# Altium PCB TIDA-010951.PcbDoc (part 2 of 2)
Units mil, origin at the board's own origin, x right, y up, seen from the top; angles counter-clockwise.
Board outline 3346.46 x 3346.46 mil, 2 copper layers (Top Layer, Bottom Layer), stack 62 mil thick; 118 components, 74 nets, 305 pads, 166 vias.
Unrouted connection lines stored in the file: 4.
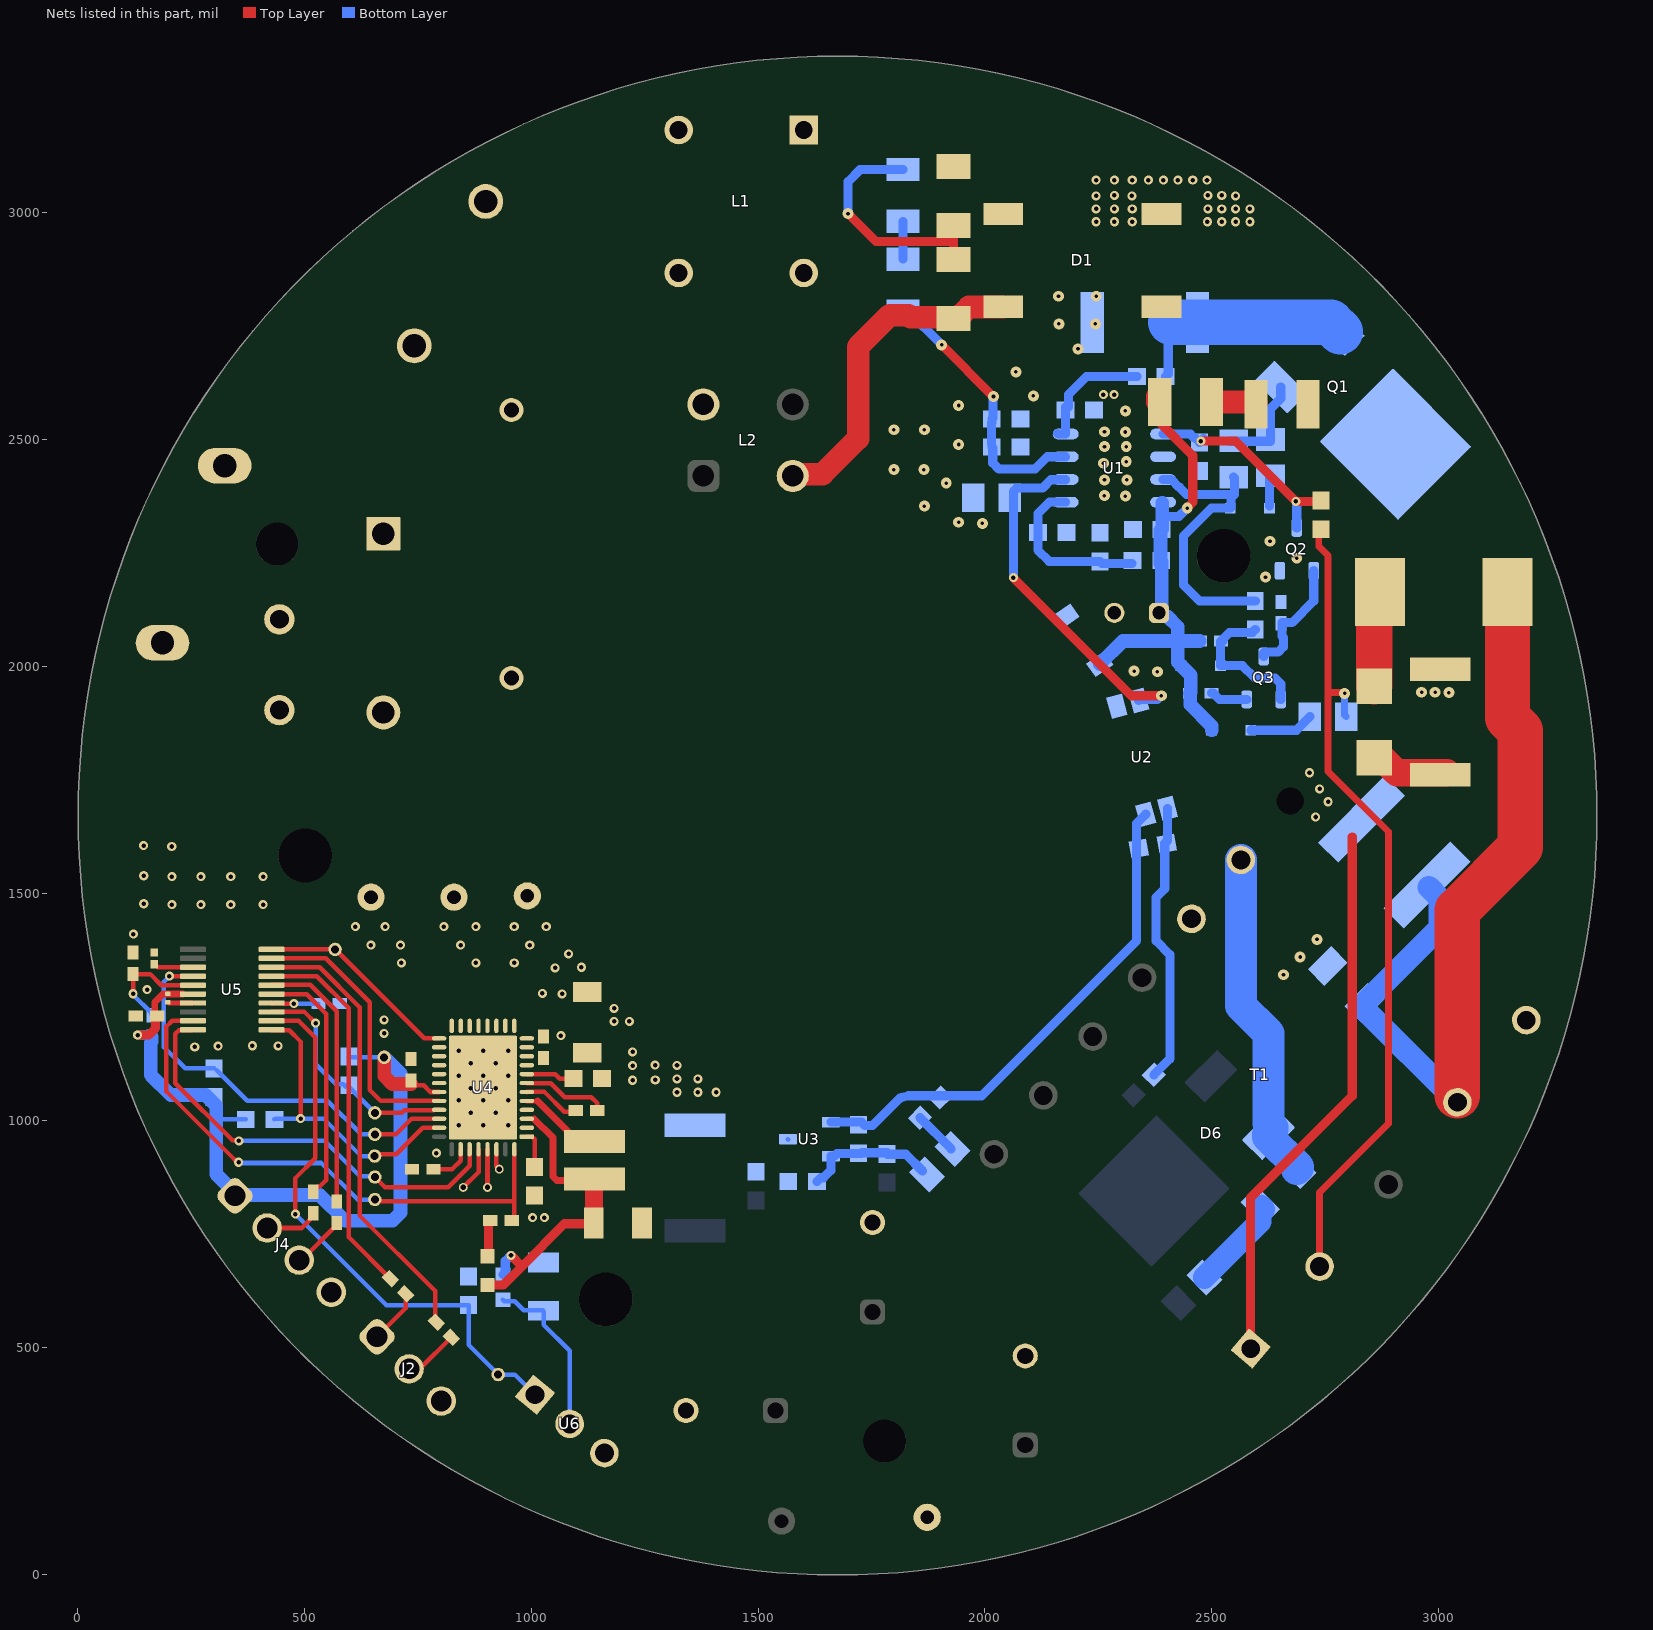
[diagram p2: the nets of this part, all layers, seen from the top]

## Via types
v1: diameter 20, hole 10, Top Layer to Bottom Layer, tented both sides, 70 vias
v2: diameter 20, hole 10, Top Layer to Bottom Layer, 51 vias
v3: diameter 24, hole 8, Top Layer to Bottom Layer, tented both sides, 45 vias

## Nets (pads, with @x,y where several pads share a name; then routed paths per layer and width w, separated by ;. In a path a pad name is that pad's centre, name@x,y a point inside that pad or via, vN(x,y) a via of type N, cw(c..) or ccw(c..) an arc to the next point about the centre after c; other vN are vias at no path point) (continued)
AVDD: C23.1 C24.2 C27.1 J4.1 R24.2 R26.2 R27.2 R34.2 TP7.1 U4.27 U5.6 | length 1746.8
  Top Layer w10: C27.1@735.64,1080.4 738.54,1077.5 763.49,1077.5 778.06,1062.92 U4.27@797.48,1062.92
  Top Layer w15: C23.1@170.7,1240.78 170.7,1260.47 188.78,1278.55 U5.6@232.4,1278.55
  Top Layer w20: v1(133.23,1188.16) 157.02,1188.16 172.69,1203.83 172.69,1228.5 174.5,1230.31 C23.1@176.18,1230.31
  Top Layer w30: TP7.1@676.21,1139.19 676.21,1098.14 693.79,1080.57 735.47,1080.57 C27.1@735.64,1080.4
  Bottom Layer w10: R24.2@158.17,1191.24 R24.2@164.37,1185.04 ; 305.94,1002.77 R26.2@371.26,1002.77 ; 404.97,836.08 407.52,838.63 ; R34.2@598.74,1140.79 600.34,1139.19 TP7.1@676.21,1139.19
  Bottom Layer w20: v1(133.23,1188.16) 155.09,1188.16 R24.2@158.17,1191.24
  Bottom Layer w30: R24.2@164.37,1185.04 163.62,1184.29 163.62,1173.44 161.65,1171.47 161.65,1100.57 206,1056.23 282.67,1056.23 305.94,1032.96 305.94,1002.77 305.94,882.34 347.67,840.6 347.67,836.08 404.97,836.08 533.97,836.08 590.66,779.38 694.66,779.38 712.23,796.96 712.23,1104.24 TP7.1@677.29,1139.19
BRAKE: TP10.1 U4.35 U5.10 | length 950.6
  Top Layer w10: U5.10@255.03,1199.95 254.13,1199.05 224.11,1199.05 216.11,1191.05 216.11,1082.35 342.02,956.44 355.22,956.44 v1(356.3,955.36) ; TP10.1@655.8,875.67 678.12,853.35 817.59,853.35 864.53,900.28 U4.35@864.53,936.82
  Bottom Layer w10: v1(356.3,955.36) 544.89,955.36 622.93,877.32 654.15,877.32 TP10.1@655.8,875.67
DRVOFF: TP6.1 U4.21 U5.20 | length 450.4
  Top Layer w10: U5.20@428.26,1377.12 TP6.1@568.19,1377.12 764.28,1181.03 U4.21@797.48,1181.03
FG: R34.1 TP11.1 U4.29 U5.13 | length 520
  Top Layer w10: U5.13@428.26,1239.32 500.61,1239.32 v1(525.41,1214.52) ; TP11.1@655.8,1017.06 714.95,1017.06 721.04,1023.15 785.98,1023.15 786.16,1023.33 786.61,1023.33 786.84,1023.55 U4.29@797.48,1023.55
  Bottom Layer w10: v1(525.41,1214.52) 525.41,1124.4 570.02,1079.79 586.56,1079.79 591.66,1074.69 596.75,1079.79 R34.1@598.74,1077.79 ; R34.1@598.38,1074.48 TP11.1@655.8,1017.06
GND: C2.1 C5.2 C6.2 C7.2 C8.2 C20.2 C21.2 C22.2 C23.2 C24.1 C25.1 C27.2 C28.2 C30.2 C31.2 C32.2 GND.1 J2.3 J4.4 R23.1 R25.2 R35.2 T1.8 U3.3 U4.2 U4.4 U4.12 U4.15 U4.18 U4.22 U4.23 U4.24 U4.25 U4.26 U4.41 U5.7 U6.3 | length 57
  Top Layer w10: C24.1@199.62,1260.5 200.44,1260.5 201.94,1259.01 U5.7@255.04,1259.01
  Bottom Layer w10: U3.3@1565.92,958.99 U3.3@1566.6,958.31
  other v1: 1003.56,786.33 1029.47,786.2 791.13,928.21 258.98,1162.35 310.35,1164.06 385.99,1164.83 442.79,1164.74 153.8,1288.53 1110.74,1337.75 123.65,1410.79 208.5,1475.89 272.28,1475.89 338.22,1475.89 409.45,1475.89 146.56,1477.77 208.5,1537.52 272.28,1537.52 338.22,1537.52 409.45,1537.52 146.56,1539.41 208.31,1603.87 146.37,1605.76
  other v2: 840.27,989.63 894.75,989.63 949.24,989.63 867.51,1016.98 921.99,1016.98 840.27,1044.32 894.75,1044.32 949.24,1044.32 867.51,1071.66 921.99,1071.66 840.27,1099 894.75,1099 949.24,1099 867.51,1126.35 921.99,1126.35 840.27,1153.69 894.75,1153.69 949.24,1153.69 1065.66,1187.01 676.21,1191.99 1182.9,1218.73 1216.47,1218.73 676.21,1221.68 1182.9,1247.16 1068.17,1279.2 1025.02,1280.01 1052.81,1336.28 1082.54,1367.27
  other v3: 2657.64,1321.25 2694.49,1360.36 2731.54,1399.13
IR: C32.1 TP15.1 U5.12 U6.1 | length 1262.2
  Top Layer w10: U5.12@428.26,1219.64 487.68,1219.64 524.26,1183.06 524.26,916.8 480.81,873.35 v1(480.81,793.8)
  Bottom Layer w10: v1(480.81,793.8) 681.1,593.5 C32.1@862.2,593.5 862.2,505.73 TP15.1@927.54,440.4 963.78,440.4 1008.26,395.92 U6.1@1008.39,395.92
LINE: pad.2 RT1.1
NetC1_1: C1.1 F1.1 L1.3 MOV1.2
NetC1_2: C1.2 L1.2 MOV1.1 RT1.2
NetC2_2: C2.2 C3.1 D1.1 D2.2 R1.2 T1.4 | length 1842.9
  Top Layer w100: T1.4@3040.9,1054.39 3040.9,1463.56 3179.6,1602.26 3179.6,1859.17 3151.32,1887.46 D2.2@3151.32,2164.37 D2.2@3151.32,2184.37
  Bottom Layer w50: C3.1@2977.56,1514.28 3002.46,1489.38 3002.46,1425.26 2829.79,1252.59 2829.19,1252 T1.4@3040.9,1040.29
NetC4_1: C4.1 R3.2 | length 215.2
  Bottom Layer w50: C4.1@2483.3,654.41 2606.41,777.52 2606.41,796.08 2614.07,803.74 2614.07,804.57 R3.2@2606.41,812.23
NetC11_1: C11.1 R7.1 R8.2 U1.1 | length 371.5
  Bottom Layer w20: U1.1@2177.86,2362.57 2177.78,2362.49 2142.08,2362.49 2116.7,2337.12 C11.1@2116.7,2295.14 2116.7,2256.68 2141.23,2232.15 R8.2@2253.26,2232.15 2258.24,2227.17 R7.1@2323.82,2227.17
NetC12_2: C12.2 Q2.3 R9.1 U1.5 | length 475.3
  Top Layer w20: v1(2475.8,2497.02) 2552.18,2497.02 v1(2685.02,2364.19) 2733.54,2364.19 R9.1@2735.19,2365.84
  Bottom Layer w20: U1.5@2392.43,2512.57 2452.43,2512.57 2461.25,2503.75 2464.15,2503.75 2472.85,2495.05 C12.2@2472.85,2494.07 v1(2475.8,2497.02) C12.2@2481.55,2502.77 ; v1(2685.02,2364.19) 2686.96,2362.24 Q2.3@2686.96,2305.8
NetC13_1: C13.1 R10.1 R13.2 U1.3 | length 596.9
  Top Layer w20: v3(1904.45,2709.03) 1904.77,2709.03 2018.59,2595.2 v3(2018.91,2595.2)
  Bottom Layer w20: R10.1@1818.98,2783.67 1829.81,2783.67 v3(1904.45,2709.03) ; C13.1@2014.31,2491.8 2014.31,2503.72 2014.75,2537.24 2015.03,2537.52 R13.2@2015.03,2545.66 2016.01,2545.66 2018.14,2547.79 2018.14,2594.43 v3(2018.91,2595.2) ; C13.1@2015.03,2483.65 2017.1,2481.58 2017.1,2449.05 2030.89,2435.26 2110,2435.26 2137.31,2462.57 U1.3@2177.86,2462.57
NetC15_1: C15.1 R15.2 U1.4 | length 282.3
  Bottom Layer w20: U1.4@2160.43,2514.24 2162.11,2512.57 U1.4@2177.86,2512.57 2177.12,2513.31 C15.1@2177.12,2571.91 ; C15.1@2177.38,2565.24 2183.91,2571.78 2183.91,2599.52 2223.51,2639.12 R15.2@2335.09,2639.12
NetC16_1: C16.1 D11.2 Q3.1 R18.2 | length 322.9
  Bottom Layer w20: R18.2@2520.14,2056.7 2518.75,2055.3 D11.2@2518.75,2002.38 2567.31,2002.38 2594.51,1975.18 2638.62,1975.18 2651.59,1962.2 Q3.1@2651.59,1927.93 ; R18.2@2524.08,2056.7 2525.89,2058.51 2525.89,2062.44 2539.07,2075.62 2589.02,2075.62 C16.1@2595.49,2082.1
NetC16_2: C16.2 D9.1 R12.1 U1.7 | length 653.7
  Bottom Layer w20: U1.7@2392.43,2412.57 2410.14,2412.57 2427.19,2395.52 2428.04,2395.52 2443.77,2379.79 2550.13,2379.79 ; R12.1@2548.03,2417.57 2550.13,2415.48 2550.13,2379.79 ; C16.2@2595.49,2145.09 2472.23,2145.09 2436.98,2180.34 2436.98,2287.39 2498.88,2349.29 D9.1@2540.35,2349.29 2542.17,2351.1 2542.17,2371.82 2550.13,2379.79
NetC17_1: C17.1 R19.1 R21.1 U2.2 U3.1 | length 1131
  Bottom Layer w20: U3.1@1660.41,996.39 1728.07,996.39 1735.55,988.91 1752.12,988.91 1812.23,1049.02 ccw(c1804.43,1067.43) 1815.56,1050.82 1831.71,1054.7 1859.31,1054.7 1883.06,1054.7 1912.49,1054.7 1992.56,1054.7 2334.01,1396.15 2334.01,1599.47 2334.01,1654.71 U2.2@2354.18,1674.88
NetC17_2: C17.2 C18.1 R16.1 R23.2 U3.2 | length 294.2
  Bottom Layer w20: R23.2@1629.59,865.38 1638.29,874.08 1644.12,874.08 1660.41,890.36 U3.2@1660.41,921.59 1668.28,921.59 1674.19,927.49 C17.2@1728.07,927.49 ; C17.2@1728.74,929.15 1784.34,929.15 R16.1@1784.34,926.67 1785.21,925.8 1825.43,925.8 C18.1@1862.34,888.89
NetC18_2: C18.2 R21.2 | length 100.3
  Bottom Layer w10: C18.2@1925.52,937.7 C18.2@1928.86,937.7
  Bottom Layer w20: R21.2@1856.92,1006.3 C18.2@1925.52,937.7
NetC19_1: C19.1 U1.2 U2.4 | length 804.2
  Top Layer w20: v1(2062.46,2196.06) 2322.62,1935.9 v3(2388.52,1935.9)
  Bottom Layer w20: v1(2062.46,2196.06) 2062.46,2386.04 2069.74,2393.32 2126.81,2393.32 2145.38,2411.88 2177.17,2411.88 U1.2@2177.86,2412.57 ; U2.4@2338.79,1925.5 2341.3,1928.01 2379.55,1928.01 2387.44,1935.9 v3(2388.52,1935.9)
NetC20_1: C20.1 C21.1 C26.1 R33.2 U4.9 U4.10 U4.11
  other v1: 1321.49,1062.42 1367.47,1062.42 1407.83,1062.42 1321.49,1092.04 1367.47,1092.04 1321.49,1121.66
  other v2: 1223.81,1088.91 1273.57,1089.82 1223.81,1121.06 1273.27,1121.98 1223.81,1151.28
NetC25_2: C25.2 U5.3 | length 88
  Top Layer w10: C25.2@170.06,1345.03 177.35,1337.75 U5.3@255.03,1337.75
NetC26_2: C26.2 U4.8 | length 106.5
  Top Layer w10: U4.8@990.63,1102.29 1053.36,1102.29 1063.46,1092.2 C26.2@1092.98,1092.2
NetC28_1: C28.1 U4.1 | length 88.4
  Top Layer w10: U4.1@990.63,964.5 1002.11,964.5 1007.97,958.64 C28.1@1007.97,890
NetC29_1: C29.1 U4.6 | length 127.1
  Top Layer w10: U4.6@990.63,1062.92 990.7,1062.99 1029.47,1062.99 1072.96,1019.5 1095.95,1019.5 C29.1@1098.61,1022.16
NetC29_2: C29.2 U4.7 | length 189.9
  Top Layer w10: U4.7@990.63,1082.61 1043.52,1082.61 1074.46,1051.67 1132.76,1051.67 1145.86,1038.57 C29.2@1145.86,1022.16
NetC30_1: C30.1 R24.1 U5.5 | length 254.2
  Top Layer w10: v1(123.03,1279.37) C30.1@123.03,1322.83 160.95,1322.83 185.41,1298.38 U5.5@255.03,1298.38 ; C30.1@128.66,1313.27 C30.1@128.66,1317.67
  Bottom Layer w10: v1(123.03,1279.37) 123.03,1277.56 164.37,1236.22 R24.1@164.37,1232.28
NetC31_1: C31.1 R29.1 U6.2 | length 374.2
  Bottom Layer w10: R29.1@937.99,605.31 941.18,602.13 963.87,602.13 983.69,582.31 1025.85,582.31 C31.1@1027.28,580.89 ; C31.1@1025.59,580.89 1027.37,579.11 1027.37,550.09 1084.99,492.48 U6.2@1084.99,330.74
NetD1_3: D1.3 D3.2 L1.1
NetD1_4: D1.4 D4.2 L2.2 | length 742.6
  Top Layer w50: L2.2@1576.4,2420.3 1580.39,2424.29 1642.24,2424.29 1720.49,2502.55 1720.49,2704.92 1790.18,2774.61 1831.6,2774.61 1836.11,2770.1 1927.81,2770.1 D4.2@1930.37,2767.54 1940.21,2767.54 1964.95,2792.28 2039.79,2792.28 D1.4@2040.29,2792.78
NetD2_1: D2.1 D5.1 | length 203.1
  Top Layer w80: D5.1@2857.95,1956.95 D2.1@2857.95,2160.09
NetD3_1: D3.1 D4.1 R5.2 | length 564.2
  Top Layer w20: v3(1698.34,2998.11) 1760.06,2936.38 1918.66,2936.38 1918.66,2960.73 D3.1@1930.37,2972.44 D4.1@1930.37,2897.46
  Bottom Layer w20: v3(1698.34,2998.11) 1698.34,3068.81 1725,3095.47 R5.2@1818.98,3095.47
NetD5_2: D5.2 R2.2 | length 156.8
  Top Layer w60: D5.2@2874.61,1799.47 2907.61,1766.48 R2.2@3017.74,1766.48
NetD6_3: D6.3 R3.1 T1.7 | length 743.4
  Bottom Layer w70: T1.7@2563.83,1574.22 2563.83,1252.9 2624.82,1191.92 2624.82,993.87 2633.78,984.91 2633.78,979.95 D6.3@2624.82,970.99 2623.37,969.54 2623.37,964.59 2690.07,897.89 2690.07,895.88 R3.1@2687.15,892.96
NetD7_2: D7.2 R6.1 | length 144.9
  Bottom Layer w20: D7.2@2587.68,1861.85 D7.2@2585.87,1860.04 2685.93,1860.04 R6.1@2715.86,1889.97
NetD9_2: D9.2 R11.1 | length 63.7
  Bottom Layer w20: D9.2@2626.89,2353.68 D9.2@2626.93,2353.73 ; R11.1@2626.93,2417.21 D9.2@2626.93,2353.73 ; D9.2@2627.04,2353.84 D9.2@2626.93,2353.73
NetD14_1: D14.1 R36.2 | length 81.8
  Top Layer w20: D14.1@903.9,700.76 906.18,703.04 R36.2@906.18,781.65
NetJ2_1: J2.1 R28.2 | length 123
  Top Layer w10: J2.1@660.51,523.54 723.4,586.42 723.4,602.94 726.18,605.72 726.18,615.36 R28.2@723.4,618.14
NetJ2_2: J2.2 R31.2 | length 122.1
  Top Layer w10: J2.2@731.22,452.83 755.03,452.83 R31.2@824.54,522.33
NetJ4_2: J4.2 R30.2 | length 112.4
  Top Layer w10: J4.2@418.38,763.3 494.64,763.3 R30.2@520.16,788.83
NetJ4_3: J4.3 R32.2 | length 114
  Top Layer w10: J4.3@494.18,692.59 572.04,770.45 R32.2@572.04,774.39
NetL1_4: L1.4 L2.3
NetL3_1: L3.1 U4.5 | length 134.9
  Top Layer w10: U4.5@990.63,1042.98 1014.35,1042.98
  Top Layer w15: 1014.35,1042.98 1080.52,976.81 1080.52,969.86 L3.1@1088.08,962.3
NetQ1_1: Q1.1 R11.2 R12.2 | length 213.7
  Bottom Layer w20: R12.2@2540.28,2496.77 R11.2@2629.09,2496.77 ; R11.2@2629.09,2500.52 2629.09,2568.25 2651.75,2590.91 Q1.1@2651.75,2615.99
NetQ1_2: Q1.2 R2.1 T1.5
  other v3: 2962.17,1943.69 2991.85,1943.69 3022.15,1942.91
NetQ1_3: Q1.3 R15.1 R17.2 | length 506
  Bottom Layer w20: R15.1@2398.08,2639.12 2403.76,2644.8 2403.76,2752.86 2409.45,2758.54
  Bottom Layer w100: 2409.45,2758.54 2762.11,2758.54 Q1.3@2782.79,2737.86
NetQ2_1: Q2.1 Q3.3 R22.2 | length 267.9
  Bottom Layer w20: Q3.3@2614.19,2022.42 2614.19,2030.3 2616,2032.11 2645.92,2032.11 2657.63,2043.82 2657.63,2063.82 2654.26,2067.19 2654.26,2097.28 2676.56,2097.28 2724.36,2145.08 Q2.1@2724.36,2211.32
NetQ3_2: Q3.2 R20.2 | length 83.4
  Bottom Layer w20: R20.2@2499.06,1941.58 2503,1941.58 2516.65,1927.93 Q3.2@2576.79,1927.93
NetR1_1: R1.1 R4.2 | length 107.6
  Top Layer w50: R4.2@2499.22,2588.32 2499.22,2583.88 2499.81,2583.29 2596.81,2583.29 2597.4,2582.7 R1.1@2597.4,2578.25
NetR5_1: R5.1 R10.2 | length 83.5
  Bottom Layer w20: R10.2@1818.98,2897.84 R5.1@1818.98,2981.3
NetR6_2: R6.2 R9.2 T1.2 | length 1838.7
  Top Layer w15: R9.2@2735.19,2302.85 2735.19,2265.61 2755.86,2244.94 2755.86,1942.91 ; T1.2@2737.22,678.38 2737.22,841.24 2889.06,993.08 2889.06,1636.32 2755.86,1769.52 2755.86,1942.91 ; v3@2790.68,1942.91 2755.86,1942.91
  Bottom Layer w15: v3(2792.32,1941.27) 2792.32,1893.52 R6.2@2795.86,1889.97
NetR14_1: R14.1 R19.2 U2.1 | length 625.1
  Bottom Layer w20: R14.1@2372.04,1100.59 2407.58,1136.13 2407.58,1365.45 2377.05,1395.99 2377.05,1491.81 2396.04,1510.81 2396.04,1610.41 2402.48,1616.84 U2.1@2402.48,1687.82
NetR25_1: R25.1 U4.34 | length 93
  Top Layer w10: R25.1@785.04,892.48 825.86,892.48 844.84,911.47 U4.34@844.84,936.82
NetR35_1: R35.1 U5.14 | length 103.6
  Top Layer w10: U5.14@428.26,1259.01 429.17,1258.1 453.62,1258.1 453.95,1257.77 v2(477.23,1257.77)
  Bottom Layer w10: v2(477.23,1257.77) R35.1@531.38,1257.77
NetTP9_1: TP9.1 U4.38 | length 46.4
  Top Layer w10: U4.38@923.58,936.82 923.58,899.2 TP9.1@929.82,892.96
NetTP16_1: TP16.1 U4.37 | length 84.1
  Top Layer w10: U4.37@903.9,936.82 U4.37@903.9,936.82 TP16.1@903.94,852.73
NetTP17_1: TP17.1 U4.36 | length 98
  Top Layer w10: TP17.1@850.61,852.73 884.21,886.34 U4.36@884.21,936.82
NetTPA_1: TPA.1 U4.13 U4.14
  other v2: 962.95,1347.59 997.01,1386.48 962.95,1427.46 1033.34,1427.46
NetTPB_1: TPB.1 U4.16 U4.17
  other v2: 878.52,1347.59 844.84,1386.48 807.75,1427.46 878.52,1427.46
NetTPC_1: TPC.1 U4.19 U4.20
  other v2: 714.42,1347.59 647.19,1386.48 712.25,1386.48 612.83,1427.46 678.56,1427.46
nFAULT: R36.1 TP12.1 U4.40 U5.9 | length 1232.6
  Top Layer w10: U5.9@261.39,1220.14 209.47,1220.14 196.65,1207.32 196.65,1064.06 347.62,913.09 348.05,913.09 353.05,908.09 v1@355.35,908.09 ; TP12.1@655.8,826.04 659.27,822.57 962.95,822.57 ; R36.1@962.95,783.46 962.95,822.57 ; U4.40@962.95,936.82 962.95,822.57
  Bottom Layer w10: v1(355.76,908.09) 357.35,906.5 537.26,906.5 617.72,826.04 TP12.1@655.8,826.04
NTRL: F1.2 pad.3
PGND: C3.2 C9.2 C11.2 C12.1 C13.2 C14.2 C15.2 C19.2 D1.2 D8.2 Q2.2 R8.1 R13.1 R17.1 R22.1 T1.1 U1.6 U2.3 | length 1220.2
  Top Layer w20: T1.1@2585.38,497.42 2585.38,830.49 2809.18,1054.29 2809.18,1624.9
  other v1: 2260.74,2599.43 2284.58,2599.43 2245.06,2980.31 2285.2,2980.31 2324.42,2980.31 2489.84,2980.31 2521.65,2980.31 2552.17,2980.31 2583.66,2980.31 2245.06,3008.86 2285.2,3008.86 2324.42,3008.86 2491.14,3008.86 2521.65,3008.86 2552.17,3008.86 2583.66,3008.86 2245.06,3037.4 2323.82,3037.4 2552.17,3037.4 2285.2,3038.39 2491.14,3038.39 2521.65,3038.39 2245.06,3071.85 2285.2,3071.85 2324.42,3071.85 2359.97,3071.85 2393.12,3071.85 2425.13,3071.85 2457.71,3071.85 2489.17,3071.85
  other v2: 2728.44,1668.86 2755.86,1702.5 2737.22,1730.71 2714.99,1766.34
  other v3: 2379.75,1988.75 2328.78,1990.24 2618.06,2197.23 2686.96,2238.88 2627.91,2276.28 1994.35,2315.84 1942.02,2318.2 1866.62,2353.84 2309.4,2375.65 2262.97,2376.85 1914.62,2404.49 2263.29,2411.61 2312.52,2411.61 1799.3,2434.08 1865.24,2434.08 2261.03,2448.29 2311.26,2451.88 2263.29,2484.99 2311.26,2484.99 1942.02,2489.68 2263.29,2517.72 2309.4,2517.12 1799.3,2522.14 1866.62,2522.14 2309.4,2563.58 1942.02,2575.42 2106.58,2596.56 2068.18,2649.44 2204.83,2700.23 2162.74,2755.42 2243.32,2755.2 2162.11,2816.28 2245.06,2816.28
RX: R28.1 U5.17 | length 833.4
  Top Layer w10: U5.17@428.26,1318.06 528.11,1318.06 598.74,1247.43 598.74,742.8 R28.1@689.99,651.55
SCL: R26.1 TP13.1 U4.31 U5.11 | length 666.1
  Top Layer w10: U5.11@428.26,1199.95 429.17,1199.05 467.12,1199.05 492.08,1174.09 v1(492.08,1004.49) ; TP13.1@655.8,925.64 702.88,925.64 761.42,984.18 U4.31@797.48,984.18
  Bottom Layer w10: R26.1@434.26,1002.77 435.97,1004.49 v1(492.08,1004.49) 542.66,1004.49 625.34,921.81 TP13.1@655.32,921.81
SDA: R27.1 TP14.1 U4.30 U5.4 | length 906
  Top Layer w10: v1(203.18,1318.06) U5.4@255.03,1318.06 ; TP14.1@655.8,969.55 702.34,969.55 736.65,1003.87 U4.30@797.48,1003.87
  Bottom Layer w10: v1(203.18,1318.06) 191.08,1305.96 191.08,1161.73 237.78,1115.02 R27.1@301.42,1115.02 ; R27.1@307.21,1110.97 374.3,1043.87 551.09,1043.87 625.4,969.55 TP14.1@655.8,969.55
SPEED: U4.28 U5.19 | length 612.5
  Top Layer w10: U5.19@428.26,1357.43 547.84,1357.43 644.77,1260.5 644.77,1067.41 668.94,1043.24 U4.28@797.48,1043.24
SWCLK: R32.1 U5.16 | length 587.1
  Top Layer w10: U5.16@428.26,1299.22 513.56,1299.22 572.04,1240.74 R32.1@572.04,821.64
SWDIO: R30.1 U5.15 | length 545.9
  Top Layer w10: U5.15@428.26,1278.55 505.43,1278.55 548.26,1235.71 548.26,868.55 533.41,853.69 526.98,853.69 520.16,846.88 R30.1@520.16,842.94
TX: R31.1 U5.18 | length 994.3
  Top Layer w10: U5.18@428.26,1337.75 534.15,1337.75 622.05,1249.85 622.05,790.97 788.34,624.67 788.34,558.52 R31.1@791.13,555.74
VBK: C22.1 D14.2 L3.2 R29.2 U4.3 | length 713.6
  Top Layer w10: U4.3@990.63,1003.87 1006.89,1003.87 ; L3.2@1136.92,868.33 L3.2@1139.95,871.36
  Top Layer w15: 1006.89,1003.87 1047.94,962.81 1047.94,877.06 1056.73,868.28 L3.2@1120.99,868.28
  Top Layer w20: D14.2@903.9,637.77 938.65,637.77 981.15,680.26 ; v1(955.71,703.04) 978.49,680.26 981.15,680.26 ; C22.1@1138.51,772.64 1073.53,772.64 981.15,680.26
  Top Layer w40: C22.1@1138.51,772.64 L3.2@1138.51,869.92
  Bottom Layer w20: R29.2@937.99,660.43 943,665.44 943,690.33 v1(955.71,703.04)
VDD: C9.1 C14.1 D7.1 D8.1 D11.1 R4.1 R7.2 R18.1 R20.1 U1.8 | length 1141.3
  Top Layer w20: R4.1@2379.48,2561.3 R4.1@2388.89,2551.89 ; R4.1@2388.89,2568.31 R4.1@2388.89,2551.89 ; R4.1@2389.35,2551.43 R4.1@2388.89,2551.89 ; v3(2445.56,2349.29) 2445.56,2350.37 2457.79,2362.6 2457.79,2464.87 2388.89,2533.77 R4.1@2388.89,2551.89
  Top Layer w50: R4.1@2380.07,2583.29 R4.1@2380.07,2595.2
  Bottom Layer w20: 2390.82,2330.93 2427.2,2330.93 v3(2445.56,2349.29)
  Bottom Layer w30: D8.1@2252.88,2005.64 2303.94,2056.7 2424.71,2056.7 ; R7.2@2386.81,2227.17 2386.81,2299.99 C14.1@2389.21,2302.39 2390.82,2303.99 2390.82,2330.93 U1.8@2390.82,2360.96 ; R7.2@2389.76,2230.62 2389.76,2112.2 2390.58,2111.39 2401.3,2111.39 2424.71,2087.97 2424.71,2056.7 ; R18.1@2472.9,2056.7 2424.71,2056.7 ; D7.1@2499.26,1860.04 2499.26,1869.41 2452.57,1916.1 2452.57,1940.84 R20.1@2451.82,1941.58 2453.79,1943.55 2453.79,1980.73 D11.1@2432.14,2002.38 2424.71,2009.8 2424.71,2056.7
pads on no net: D6.1 L2.1 L2.4 T1.3 T1.6 T1.9 T1.10 T1.11 T1.12 U4.32 U4.33 U4.39 U5.1 U5.2 U5.8

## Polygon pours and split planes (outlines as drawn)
PGND on Bottom Layer "BOTTOM_LAYER_PGND_P146" (solid, pour order 146): 2690.07,1672.03 2690.07,1800 2883.93,1800 2925,1758.93 2925,1702.5 2786.83,1564.33 2738.21,1564.33 2738.21,1567.51 2690.07,1615.64
PGND on Bottom Layer "BOTTOM_LAYER_PGND_P128" (solid, remove dead copper, pour order 128): 2192.75,1961.29 2168,1996.18 2121.19,2062.15 2051.9,2127.03 1994.4,2169.78 1874.24,2231.7 1768.09,2253.82 1767.33,2663 2195.87,3091.54 2746.02,3091.54 2746.02,1893.52 2219.97,1893.52
+24V on Bottom Layer "Bottom Layer-+24V" (solid, pour order 147): 1449.82,151.65 1548.16,53.31 1601.03,0.45 1750.3,0.49 1907.91,15.06 2083.39,53.31 2137.49,65.1 2228.43,92.91 2334.78,134.29 2435.79,181.66 2468.49,591.68 2420.18,643.84 2409.72,719.61 2539.15,852.82 2493,898.98 2379.55,1012.42 2379.55,1034.51 2328.78,1085.28 2058.57,1085.28 1838.01,886.06 1707.35,886.06 1659.63,847.37 1470.03,845.16 1470.03,777.49 1295.21,777.49 1296.26,776.43 1296.26,643.84 1449.82,490.28
NetQ1_2 on Bottom Layer "BOTTOM_LAYER_NETQ1_2_P111" (solid, pour order 111): 2909.43,1863.96 3095.49,1677.9 3095.49,1241.01 3146.76,1189.74 3218.5,1189.74 3310.38,1307.62 3316.06,1344.5 3338.6,1490.99 3348.42,1636.66 3348.42,1748.42 3326.81,1940.12 3306.69,2043.43 3275.25,2161.45 3247.84,2243.43 3198.23,2364.9 3121.11,2514.06 3076.63,2586.18 3032.75,2650.16 2970.19,2731.6 2738.21,2494.11 2909.43,2322.89
GND on Bottom Layer "Bottom Layer-GND" (solid, pour order 149): 1.97,1629.37 10.65,1501.83 34.29,1344.74 73.92,1186.65 131.43,1026.69 211.9,860.57 292.8,732.29 359.7,638.02 464.75,516.82 610.59,381.17 741.67,283.43 875.74,202.14 1018.51,133.05 1180.12,73.72 1289.15,43.95 1388.1,23.62 1504.99,7.48 1506.51,22.82 1504.99,66.81 1506.51,75.91 1430.02,160.61 1430.02,483.12 1275.12,638.02 1275.12,865.38 1537.07,865.38 1537.07,824.73 1551.98,809.82 1593.82,809.82 1593.82,1076.8 1593.82,1090.41 1468.36,1121.16 1467.12,1119.93 1467.12,932.85 1466.53,932.85 1448.77,915.09 1275.12,915.09 1275.12,1010.01 1230.34,1053.84 1132.36,1052.54 1110.15,1070.48 1110.15,1194.16 1128.84,1204.73 1242.21,1205.32 1289.15,1228.99 1226.08,1289.67 1175.32,1365.81 1132.36,1446.66 1097.76,1543.96 1087.89,1639.85 1088.88,1688.6 2.69,1688.6
GND on Bottom Layer "BOTTOM_LAYER_GND_P145" (solid, pour order 145): 2851.44,1397.15 2850,1398.59 2768.37,1480.22 2661.61,1480.22 2640.74,1459.35 2640.74,1300.23 2699.56,1241.41 2851.44,1393.29
NetTPC_1 on Bottom Layer "BOTTOM_LAYER_NETTPC_1_P118" (solid, pour order 118): 565.93,1434.62 565.93,1541.67 583.48,1559.23 705.45,1559.23 705.45,1557.34 731.11,1531.68 731.11,1421.9 850.78,1224.64 850.78,1191.99 822.78,1191.99 613.58,1386.97
NetTPB_1 on Bottom Layer "BOTTOM_LAYER_NETTPB_1_P119" (solid, pour order 119): 753.44,1537.52 753.44,1456.69 878.49,1220.7 878.49,1193.93 911.13,1193.93 910.08,1194.98 910.08,1525.29 876.87,1558.51 773.39,1558.51 773.39,1557.47
NetTPA_1 on Bottom Layer "BOTTOM_LAYER_NETTPA_1_P112" (solid, pour order 112): 933.8,1197.68 933.8,1539.9 952.41,1558.51 1054.71,1558.51 1073.82,1539.4 1068.17,1423.85 967.04,1221 967.04,1192.9 938.93,1192.9 938.76,1192.72
NetC1_2 on Bottom Layer "BOTTOM_LAYER_NETC1_2_P137" (solid, pour order 137): 877.95,2584.65 628.94,2335.63 628.94,2234.06 622.05,2227.17 622.05,2207.28 665.06,2164.27 810.72,2164.27 1073.82,2427.37 1073.82,3027.56 1179.13,3132.87 1441.67,3132.87 1484.25,3175.45 1484.25,3293.76 1460.09,3317.91 877.95,3317.91
LINE on Bottom Layer "BOTTOM_LAYER_LINE_P138" (solid, pour order 138): 725.39,2872.05 221.46,2474.65 221.46,2350.39 241.14,2330.71 403.48,2349.7 835.63,2731.32 835.63,2872.05
NTRL on Bottom Layer "BOTTOM_LAYER_NTRL_P132" (solid, pour order 132): 502.21,2147.27 502.21,2074.29 482.3,2054.38 301.42,2054.38 216.54,1989.17 98.43,1989.17 98.43,2139.62 106.08,2147.27 118.49,2147.27
NetL1_4 on Bottom Layer "BOTTOM_LAYER_NETL1_4_P139" (solid, pour order 139): 1641.34,2931.1 1719.58,2931.1 1721.4,2932.93 1723.43,2930.9 1723.43,2789.75 1462.89,2529.22 1329.03,2529.22 1329.03,2648.07 1613.89,2932.93 1652.06,2932.93
NetC1_1 on Bottom Layer "BOTTOM_LAYER_NETC1_1_P131" (solid, pour order 131): 574.7,2001.66 810.99,2001.66 1160.96,2351.62 1160.96,2847.33 1258.76,2945.13 1427.36,2945.13 1451.77,2920.72 1451.77,2840.76 1413.18,2802.17 1345.92,2802.17 1345.92,2800.65 1292.71,2747.44 1292.71,2209.36 939.56,1856.2 409.45,1856.2 409.45,1927.22
NetC20_1 on Bottom Layer "BOTTOM_LAYER_NETC20_1_P120" (solid, pour order 120): 1428.44,969.55 1293.31,969.55 1292.71,970.15 1292.71,1018.22 1290.3,1018.22 1234.71,1073.82 1131.09,1073.82 1131.09,1185.13 1337.66,1185.13 1428.44,1094.35
PGND on Top Layer "TOP_LAYER_PGND_P143" (solid, remove dead copper, pour order 143): 2470.94,3091.54 2593.26,3091.54 2715.71,2969.09 2715.71,2897.46 2355.13,2897.46 2305.12,2847.45 2305.12,2727.64 2342.84,2689.92 2342.84,2680.19 2505.31,2517.72 2694.34,2517.72 2823.82,2388.24 2823.82,1604.94 2608.21,1604.94 2017.09,2196.06 1851.49,2196.06 1786.48,2261.07 1786.48,2552.97 1919.53,2686.02 2132.34,2686.02 2132.34,3038.39 2185.49,3091.54
GND on Top Layer "TOP_LAYER_GND_P136" (solid, remove dead copper, pour order 136): 2333.39,853.74 2746.02,1266.37 2746.02,1454.64 2250.49,1524.74 2210.77,1418.56 2098.28,1266.37 1917.84,1139.69 1732.71,1083.45 1607.24,1088.59 1440.27,1127.51 1303.12,1213.51 1220.18,1295.94 1138.7,1429.08 1095.77,1577.5 1090.03,1684.28 1043.52,1684.28 6.39,1684.28 8.46,1524.74 24.92,1395.83 66.02,1213.51 169.53,942.2 298.57,720.93 417.93,567.95 604.88,385.9 769.75,264.96 921.32,178.25 1176.04,74.02 1433.78,16.31 1707.4,-0.89 1948.99,21.35 2151.91,68.15 2333.39,133.69
NetC2_2 on Top Layer "TOP_LAYER_NETC2_2_P144" (solid, remove dead copper, pour order 144): 2342.79,2816.28 2870.33,2816.28 3111.28,2498.51 3199.83,2284.37 3208.37,2246.23 3208.37,2091.12 3022.15,2093.19 2991.14,2124.2 2991.14,2294.29 2786.93,2498.51 2713.56,2498.51 2680.78,2531.28 2680.78,2570.9 2680.78,2656.6 2678.79,2658.59 2678.79,2678.13 2442.14,2678.13 2388.52,2731.74 2344.76,2731.74
NetD1_3 on Top Layer "TOP_LAYER_NETD1_3_P134" (solid, pour order 134): 2079.09,3064.96 2078.99,3064.86 2078.99,2974 2005.52,2974 1994.35,2985.18 1994.35,3050 1981.6,3062.75 1981.6,3064.96 1649.11,3064.96 1560.21,3153.86 1560.21,3250 2015.66,3250 2079.09,3186.57
NetTPA_1 on Top Layer "TOP_LAYER_NETTPA_1_P106" (solid, pour order 106): 938.58,1192.9 938.76,1192.72 967.04,1192.9 968.44,1222.41 1068.17,1423.85 1068.17,1556.95 950.85,1556.95 933.8,1539.9 933.8,1302.76 938.58,1240.15
NetC20_1 on Top Layer "TOP_LAYER_NETC20_1_P124" (solid, pour order 124): 978.82,1164.83 979.01,1164.64 1005.14,1164.64 1005.14,1164.06 1017.7,1151.51 1082.54,1151.51 1100.47,1169.44 1382.81,1169.44 1445.85,1106.41 1445.85,1042.98 1273.27,1042.98 1244.85,1071.4 1137.76,1071.4 1137.76,1109.29 1125.99,1121.06 1010.36,1121.06 1004.73,1115.44 975.43,1115.44 975.43,1164.53 979.03,1164.53
NetTPC_1 on Top Layer "TOP_LAYER_NETTPC_1_P123" (solid, pour order 123): 824.54,1193.93 565.93,1427.46 565.93,1541.67 583.48,1559.23 705.45,1559.23 705.45,1557.34 723.4,1539.4 723.4,1434.62 849.04,1226.38 849.04,1193.93
NetTPB_1 on Top Layer "TOP_LAYER_NETTPB_1_P122" (solid, pour order 122): 878.49,1220.7 878.52,1220.73 757.6,1448.84 757.6,1541.28 774.61,1558.29 776.72,1556.17 874.61,1556.17 906.26,1524.52 911.13,1193.93 878.49,1193.93 878.48,1193.94 878.49,1220.73

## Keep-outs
Keep-Out Layer:
  circle w10: c1675.2,1674.21 r1672.74
  circle w10: c1675.2,1674.21 r588.93
  lines w10: 324.98,1758.86 324.98,1770.66 333.85,1779.53 910.16,1779.53 917.32,1772.36 917.32,1758.86 910.61,1752.14 331.69,1752.14 324.98,1758.86
  text ".Layer_Name" at 577,-858.49 h25

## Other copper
Top Layer:
  rectangle net NetQ1_2: 2937.34,1915.65 3046.23,2004.08
Bottom Layer:
  pour cut-out: 2712.6,2405.51 2712.44,2405.35 2712.44,2207.9 2746.84,2207.9 2746.84,2405.28 2712.09,2405.28 2711.4,2405.97

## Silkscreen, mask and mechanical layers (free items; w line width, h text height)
Top Overlay:
  text "-" at 2397.67,3078.21 h25
  text "+" at 2397.67,2693.78 h25
  text "TIDA-010951" at 1803.49,2602.97 h60
  text "NTRL" at 252.09,2328.87 h25
  text "LINE" at 131.51,1935.22 h25
  text ".Layer_Name" at 577,-858.49 h25
Bottom Overlay:
  text "AVDD" at 411.42,890.18 h20 r315
  text "SWDIO" at 489.1,808.99 h20 r315
  text "SWCLK" at 573.05,723 h20 r315
  text "GND" at 636.14,658.27 h20 r315
  text "RX" at 723.4,558.58 h20 r315
  text "TX" at 789.78,496.07 h20 r315
  text "GND" at 875.87,424.48 h20 r315
  text ".Layer_Name" at 577,-858.49 h25
Top Paste:
  text ".Layer_Name" at 577,-858.49 h25
Bottom Paste:
  text ".Layer_Name" at 577,-858.49 h25
Top Solder:
  text ".Layer_Name" at 577,-858.49 h25
  text ".Layer_Name" at 577,-858.49 h25
Bottom Solder:
  text ".Layer_Name" at 577,-858.49 h25
Drill Guide:
  text ".Layer_Name" at 577,-858.49 h25
M1 Board Outline:
  circle w10: c1675.2,1674.21 r588.94
  pour cut-out: 1675.2,1085.28 cw(c1675.2,1674.21) 1086.26,1674.21 cw(c1675.2,1674.21) 1675.2,2263.15 cw(c1675.2,1674.21) 2264.13,1674.21 cw(c1675.2,1674.21)
  pour cut-out: 1675.2,1085.28 cw(c1675.2,1674.21) 1086.26,1674.21 cw(c1675.2,1674.21) 1675.2,2263.15 cw(c1675.2,1674.21) 2264.13,1674.21 cw(c1675.2,1674.21)
  pour cut-out: 1675.2,1085.28 cw(c1675.2,1674.21) 1086.26,1674.21 cw(c1675.2,1674.21) 1675.2,2263.15 cw(c1675.2,1674.21) 2264.13,1674.21 cw(c1675.2,1674.21)
  lines w10: 3347.94,1674.21 ccw(c1675.2,1674.21) 3347.94,1674.21
  text ".Layer_Name" at 577,-858.49 h25
M2 Board Dimensions:
  rectangle: 125,-400 500,-275
  rectangle: 0,-275 125,-150
  lines w7: 0,-275 1000,-275 ; 125,-400 125,-150 ; 250,-400 250,-150 ; 500,-400 500,-150 ; 750,-400 750,-150 ; 0,-400 0,-150 1000,-150 1000,-400 0,-400
  text ".Layer_Name" at 577,-858.49 h25
M3 3D STEP Top:
  text ".Layer_Name" at 577,-858.49 h25
M4 3D STEP Bottom:
  text ".Layer_Name" at 577,-858.49 h25
Top M5 Assembly Top/M6 Assembly Bottom:
  lines w10: -292,-930.17 6308,-930.17 ; -292,-726.83 6310,-726.83 ; -292,-523.5 -292,-1133.5 3713,-1133.5 6310,-1133.5 6310,-523.5 -291.5,-523.5 -291.5,-1133.5 1284,-1133.5 ; 2173,-1133.5 2173,-523.5 ; 3440,-726.83 3440,-523.5 ; 4280,-726.83 4280,-523.5 ; 4902,-1140 4902,-937.17
  text "COMPONENTS MARKED 'DNP' SHOULD NOT BE POPULATED." at 1153.5,-318.5 h25
  text "ASSEMBLY VARIANT:" at 1153,-434 h25
  text ".VariantName" at 2189,-434 h25
  text "PCB VIEWED FROM TOP SIDE" at -228.5,-655.67 h25
  text "BOARD #:" at 2248,-655.67 h25
  text ".PRJ_Number" at 2793.5,-655.67 h25
  text "REV:" at 3638,-655.67 h25
  text ".PCB_Rev" at 3929.5,-655.67 h25
  text "SVN REV:" at 4476,-655.67 h25
  text ".VersionControl_RevNumber" at 4982,-655.67 h25
  text "PLOT NAME =" at -228.5,-1064.34 h25
  text ".plot_File_Name" at 577,-1064.34 h25
  text "GENERATED    :" at 2250,-1064.34 h25
  text ".Print_Date" at 3119.5,-1064.34 h25
  text ".Print_Time" at 3848.5,-1064.34 h25
  text "TEXAS INSTRUMENTS" at 5113,-1064.34 h25
Bottom M5 Assembly Top/M6 Assembly Bottom:
  lines w10: -292.5,-727.33 6309.5,-727.33 ; -290.5,-930.67 6309.5,-930.67 ; 1115.5,-1140.5 1115.5,-937.67 ; 1737.5,-727.33 1737.5,-524 ; 2577.5,-727.33 2577.5,-524 ; 3844.5,-1134 3844.5,-524 ; 4733.5,-1134 6309,-1134 6309,-524 -292.5,-524 -292.5,-1134 2304.5,-1134 6309.5,-1134 6309.5,-524
  text "COMPONENTS MARKED 'DNP' SHOULD NOT BE POPULATED." at 6102,-318 h25
  text ".VariantName" at 5058,-434 h25
  text "ASSEMBLY VARIANT:" at 6097,-434 h25
  text ".VersionControl_RevNumber" at 1035.5,-656.17 h25
  text "SVN REV:" at 1541.5,-656.17 h25
  text ".PCB_Rev" at 2088,-656.17 h25
  text "REV:" at 2379.5,-656.17 h25
  text ".PRJ_Number" at 3224,-656.17 h25
  text "BOARD #:" at 3769.5,-656.17 h25
  text "PCB VIEWED FROM BOTTOM SIDE" at 6246,-656.17 h25
  text "TEXAS INSTRUMENTS" at 904.5,-1064.84 h25
  text ".Print_Time" at 2169,-1064.84 h25
  text ".Print_Date" at 2898,-1064.84 h25
  text "GENERATED    :" at 3767.5,-1064.84 h25
  text ".plot_File_Name" at 5440.5,-1064.84 h25
  text "PLOT NAME =" at 6246,-1064.84 h25
M9 Title Sheet:
  drawing of 56 lines, arcs and shapes, not listed
  text "1" at 1058.34,13381.39 h25
  text "2" at 4384,13381.39 h25
  text "3" at 7714,13381.39 h25
  text "4" at 11049,13381.39 h25
  text "5" at 14374,13381.39 h25
  text "6" at 17709,13381.39 h25
  text "A" at -463,11603.39 h25
  text "A" at 19237,11603.39 h25
  text "B" at -463,7853.39 h25
  text "B" at 19237,7853.39 h25
  text "C" at -463,4103.39 h25
  text "C" at 19237,4103.39 h25
  text "D" at -463,353.39 h25
  text "D" at 19237,353.39 h25
  text "PROJECT TITLE:" at 16143,268.39 h25
  text ".PRJ_Title" at 16193,135.06 h25
  text "DESIGNED FOR:" at 16143,-32.61 h25
  text ".PRJ_Customer" at 16193,-172.61 h25
  text "FILE NAME:" at 16143,-332.61 h25
  text ".PCB_File_Name_No_Path" at 16193,-452.61 h25
  text "Texas Instruments (TI) and/or its licensors do not warrant the accuracy or completeness of this specification" at 11173.5,-614.45 h25
  text "ENGINEER:" at 16143,-622.61 h25
  text "LAYOUT BY:" at 17648,-622.61 h25
  text "or any information contained therein. TI and/or its licensors do not warrant that this design will meet" at 11128.51,-727.11 h25
  text ".PRJ_Engineer" at 16193,-777.6 h25
  text ".PCB_Layout" at 17698.5,-777.6 h25
  text "the specifications, will be suitable for your application or fit for any particular purpose, or will operate in" at 11128.51,-839.78 h25
  text ".Layer_Name" at 577,-858.49 h25
  text "ALTIUM DESIGNER VERSION:" at 17648,-932.61 h25
  text "an implementation. TI and/or its licensors do not warrant that the design is production worthy. You should" at 11128.51,-952.44 h25
  text "completely validate and test your design implementation to confirm the system functionality for your application." at 11173.5,-1065.11 h25
  text ".print_Scale" at 16193,-1065.94 h25
  text ".Application_BuildNumber" at 17698.5,-1065.94 h25
  text "1" at 1058.34,-1318.61 h25
  text "2" at 4384,-1318.61 h25
  text "3" at 7714,-1318.61 h25
  text "4" at 11049,-1318.61 h25
  text "5" at 14374,-1318.61 h25
  text "6" at 17709,-1318.61 h25
M10 Fab Notes:
  drawing of 189 lines, arcs and shapes, not listed
  text "DESIGN INFORMATION" at 17178.02,6365.17 h25
  text "MIN. TRACK WIDTH:" at 16533.46,6233.05 h25
  text "8" at 17629.7,6233.05 h25
  text "MIL" at 17784.46,6233.05 h25
  text "MIN. CLEARANCE:" at 16533.46,6108.92 h25
  text "MIL" at 17784.46,6108.92 h25
  text "7.874" at 17459.65,6104.33 h25
  text "MIN. VIA PAD SIZE:" at 16533.46,5984.8 h25
  text "24" at 17599.71,5984.8 h25
  text "MIL" at 17784.46,5984.8 h25
  text "0.05mm (2MIL)" at 17228.46,5854.9 h25
  text "MINIMUM ANNULAR RING" at 16204.23,5846.67 h25
  text "EXTERNAL" at 17936.46,5846.67 h25
  text "PER" at 16404.23,5736.55 h25
  text "IPC-D-275 CLASS 2 LEVEL C" at 16624.23,5736.54 h25
  text "MIL, HOLES" at 18112.46,5636.07 h25
  text "+/-" at 17720,5627.48 h25
  text "+/-" at 18574,5627.48 h25
  text "REGISTRATION TOLERANCES:" at 16204.23,5626.42 h25
  text "METAL" at 17404,5626.42 h25
  text "5" at 17980.2,5626.42 h25
  text "3" at 18813.2,5626.42 h25
  text "MIL" at 18929.46,5626.42 h25
  text "HOLE SIZE TOLERANCE (UNLESS OTHERWISE SPECIFIED):" at 16204.23,5528.1 h25
  text "+/-" at 18574,5525.23 h25
  text "3" at 18813.2,5524.17 h25
  text "MIL" at 18929.46,5524.17 h25
  text "MATERIAL:" at 16129.46,5386.52 h25
  text "FR-4 High Tg" at 17115.9,5258 h25
  text "X" at 16971.46,5250.01 h25
  text "FR-4" at 16550.46,5245.49 h25
  text "OTHER" at 18038.46,5245.49 h25
  text "62 MIL (1.6mm) +/-10%" at 16870.56,5102.46 h25
  text "X" at 16750.46,5100.01 h25
  text "THICKNESS:" at 16204.23,5094.24 h25
  text "OTHER" at 18155.46,5094.24 h25
  text "TOLERANCE:" at 16204.23,4955.92 h25
  text "X" at 17052.46,4955.92 h25
  text "ANSI IPC-6012 TYPE 3 CLASS 2" at 17230.48,4955.92 h25
  text "OTHER +/-" at 17230.46,4811.73 h25
  text "BOW & TWIST:" at 16204.23,4666.54 h25
  text "X" at 17052.46,4666.54 h25
  text "ANSI IPC-6012 TYPE 3 CLASS 2" at 17230.48,4666.54 h25
  text "OTHER +/-" at 17230.46,4519.85 h25
  text "DRILLING:" at 16129.46,4389.23 h25
  text "NC_DRILL FILES" at 17890.46,4284.04 h25
  text "REFERENCE:" at 16204.23,4280.1 h25
  text "X" at 16861.46,4280.01 h25
  text "AS SHOWN" at 17039.46,4280.1 h25
  text "X" at 17762.46,4280.1 h25
  text "OTHER" at 18188.46,4137.85 h25
  text "PTH COPPER THICKNESS:" at 16203.91,4134.32 h25
  text "X" at 17343.14,4134.32 h25
  text "20-30 um" at 17471.14,4134.32 h25
  text "BOARD FINISH:" at 16129.46,3986.73 h25
  text "SILKSCREEN:" at 16284.68,3876.6 h25
  text "X" at 17242.46,3876.6 h25
  text "TOP" at 17359.46,3876.6 h25
  text "X" at 17752.46,3876.6 h25
  text "BOTTOM" at 17870.46,3876.6 h25
  text "SILKSCREEN COLOR:" at 16284.68,3721.41 h25
  text "X" at 17241.46,3721.41 h25
  text "WHITE" at 17359.46,3721.41 h25
  text "OTHER" at 17870.46,3721.41 h25
  text "X" at 17372.46,3577.96 h25
  text "GREEN" at 17490.46,3577.96 h25
  text "OTHER" at 18108.46,3577.96 h25
  text "SOLDER RESIST COLOR:" at 16284.68,3571.1 h25
  text "X" at 17372.46,3423.71 h25
  text "MATTE" at 17490.46,3423.71 h25
  text "SEMI-GLOSS" at 18108,3423.07 h25
  text "IMMERSION GOLD (ENIG)" at 17190.46,3250.94 h25
  text "ENEPIG" at 18528,3243.72 h25
  text "SURFACE FINISH:" at 16129.46,3242.72 h25
  text "X" at 17012.46,3242.72 h25
  text "IMM. TIN/SILVER OR EQUIV" at 16459,3105.4 h25
  text "OTHER" at 17890.46,3101.47 h25
  text "ARRAY/PANEL:" at 16129.46,2946.09 h25
  text "CUT AND TRIM PER M1 BOARD OUTLINE" at 17190.46,2937.87 h25
  text "N.C. ROUTE" at 17190.46,2801.9 h25
  text "X" at 17878.46,2801.9 h25
  text "V. SCORE" at 18056.46,2801.9 h25
  text "CERTIFICATION:" at 16129.46,2672.77 h25
  text "MATERIALS AND WORKMANSHIP FOR ALL PCBS" at 16854.46,2672.77 h25
  text "TO MEET OR EXCEED THE REQUIREMENTS OF:" at 16854.46,2578.71 h25
  text "X" at 16491.97,2450.08 h25
  text "ANSI IPC-A-600F CLASS ->" at 16619.96,2450.08 h25
  text "X" at 18267.97,2450.08 h25
  text "2" at 18377.96,2450.08 h25
  text "1" at 18062.96,2448.58 h25
  text "3" at 18731.96,2448.58 h25
  text "X" at 17303.97,2302.39 h25
  text "RoHS" at 17431.96,2302.39 h25
  text "OTHER" at 18076.36,2302.39 h25
  text "PER ORDER" at 18473.42,2302.39 h25
  text "ALL BOARDS MUST MEET OR EXCEED UL94-V0 REQUIREMENTS." at 16157,2148.57 h25
  text "PCB MUST BEAR THE UL94V-0 UL REGISTERED MATERIAL ID NUMBER" at 16157,2032.5 h25
  text "ADDITIONAL REQUIREMENTS:" at 16129.46,1863.08 h25
  text "MICROSECTION:" at 16204.23,1755.95 h25
  text "YES" at 17109.96,1755.95 h25
  text "REQUIRED" at 17971.46,1611.62 h25
  text "BARE BOARD ELEC. TEST:" at 16204.23,1608.76 h25
  text "NONE" at 17509.96,1608.76 h25
  text "X" at 17853.46,1608.76 h25
  text "PER ORDER" at 18563.46,1608.76 h25
  text "XX MIL VIAS REQUIRE NON-CONDUCTIVE FILL AND PLANARIZE" at 16372.38,1403.82 h25
  text "XX MIL VIAS REQUIRE CONDUCTIVE FILL AND PLANARIZE" at 16380.38,1299.84 h25
  text "OUTER XX MIL TRACES REQUIRE 50 OHM SINGLE-ENDED IMPEDANCE" at 16379.39,1136.46 h25
  text "LAYER 2 & 3 (INNER LAYERS) XX MIL WIDE, XX MIL SPACE / TRACES REQUIRE 100 OHM DIFFERENTIAL IMPEDANCE" at 16371.39,900.74 h25
  text ".Layer_Name" at 577,-858.49 h25
M11 Gerber Information:
  lines w10: -292,-930.17 6308,-930.17 ; -292,-726.83 6310,-726.83 ; -292,-523.5 -292,-1133.5 3713,-1133.5 6310,-1133.5 6310,-523.5 -291.5,-523.5 -291.5,-1133.5 1284,-1133.5 ; 2173,-1133.5 2173,-523.5 ; 3440,-726.83 3440,-523.5 ; 4280,-726.83 4280,-523.5 ; 4902,-1140 4902,-937.17
  text "ALL ARTWORK VIEWED FROM TOP SIDE" at -228.5,-655.67 h25
  text "BOARD #:" at 2248,-655.67 h25
  text ".PRJ_Number" at 2793.5,-655.67 h25
  text "REV:" at 3638,-655.67 h25
  text ".PCB_Rev" at 3929.5,-655.67 h25
  text "SVN REV:" at 4476,-655.67 h25
  text ".VersionControl_RevNumber" at 4982,-655.67 h25
  text "LAYER NAME =" at -228.5,-858.49 h25
  text "PLOT NAME =" at -228.5,-1064.34 h25
  text ".plot_File_Name" at 577,-1064.34 h25
  text "GENERATED    :" at 2250,-1064.34 h25
  text ".Print_Date" at 3119.5,-1064.34 h25
  text ".Print_Time" at 3848.5,-1064.34 h25
  text "TEXAS INSTRUMENTS" at 5113,-1064.34 h25
M12 Stackup:
  drawing of 198 lines, arcs and shapes, not listed
  text "Layer" at 14570.06,13143.98 h25
  text "Name" at 14752.52,13143.98 h25
  text "Material" at 15151.58,13143.98 h25
  text "Thickness" at 15521.49,13143.98 h25
  text "Constant" at 15803.92,13143.98 h25
  text "Board Layer Stack" at 16053.03,13143.98 h25
  text "Top Overlay" at 14752.52,13093.98 h25
  text "Top Solder" at 14752.52,13043.98 h25
  text "Solder Resist" at 15151.58,13043.98 h25
  text "0.40mil" at 15521.49,13043.98 h25
  text "3.5" at 15803.92,13043.98 h25
  text "1" at 14570.06,12993.98 h25
  text "Top Layer" at 14752.52,12993.98 h25
  text "1.40mil" at 15521.49,12993.98 h25
  text "Dielectric1" at 14752.52,12943.98 h25
  text "FR-4 High Tg" at 15151.58,12943.98 h25
  text "59.20mil" at 15521.49,12943.98 h25
  text "4.8" at 15803.92,12943.98 h25
  text "2" at 14570.06,12893.98 h25
  text "Bottom Layer" at 14752.52,12893.98 h25
  text "1.40mil" at 15521.49,12893.98 h25
  text "Bottom Solder" at 14752.52,12843.98 h25
  text "Solder Resist" at 15151.58,12843.98 h25
  text "0.40mil" at 15521.49,12843.98 h25
  text "3.5" at 15803.92,12843.98 h25
  text "Bottom Overlay" at 14752.52,12793.98 h25
  text ".Layer_Name" at 577,-858.49 h25
M13 Component Bodies Top:
  text ".Layer_Name" at 577,-858.49 h25
M14 Component Bodies Bottom:
  text ".Layer_Name" at 577,-858.49 h25
M15 Courtyards Top:
  text ".Layer_Name" at 577,-858.49 h25
M16 Courtyards Bottom:
  text ".Layer_Name" at 577,-858.49 h25
Drill Drawing:
  drawing of 162 lines, arcs and shapes, not listed
  text "Symbol" at 5397.08,3431.75 h30
  text "Quantity" at 5522.3,3431.75 h30
  text "Finished Hole Size" at 5660.65,3431.75 h30
  text "Plated" at 5925.8,3431.75 h30
  text "Hole Type" at 6033.75,3431.75 h30
  text "Drill Layer Pair" at 6190.05,3431.75 h30
  text "Hole Tolerance" at 6491.46,3431.75 h30
  text "45" at 5522.3,3379.95 h25
  text "8.00mil (0.203mm)" at 5660.65,3379.95 h25
  text "PTH" at 5925.8,3379.95 h25
  text "Round" at 6033.75,3379.95 h25
  text "Top Layer - Bottom Layer" at 6190.05,3379.95 h25
  text "121" at 5522.3,3328.16 h25
  text "10.00mil (0.254mm)" at 5660.65,3328.16 h25
  text "PTH" at 5925.8,3328.16 h25
  text "Round" at 6033.75,3328.16 h25
  text "Top Layer - Bottom Layer" at 6190.05,3328.16 h25
  text "C" at 5382.53,3318.17 h23.02
  text "3" at 5522.3,3276.37 h25
  text "11.81mil (0.300mm)" at 5660.65,3276.37 h25
  text "PTH" at 5925.8,3276.37 h25
  text "Round" at 6033.75,3276.37 h25
  text "Top Layer - Bottom Layer" at 6190.05,3276.37 h25
  text "8" at 5522.3,3224.58 h25
  text "17.72mil (0.450mm)" at 5660.65,3224.58 h25
  text "PTH" at 5925.8,3224.58 h25
  text "Round" at 6033.75,3224.58 h25
  text "Top Layer - Bottom Layer" at 6190.05,3224.58 h25
  text "2" at 5522.3,3172.79 h25
  text "29.53mil (0.750mm)" at 5660.65,3172.79 h25
  text "PTH" at 5925.8,3172.79 h25
  text "Round" at 6033.75,3172.79 h25
  text "Top Layer - Bottom Layer" at 6190.05,3172.79 h25
  text "5" at 5522.3,3120.99 h25
  text "30.00mil (0.762mm)" at 5660.65,3120.99 h25
  text "PTH" at 5925.8,3120.99 h25
  text "Round" at 6033.75,3120.99 h25
  text "Top Layer - Bottom Layer" at 6190.05,3120.99 h25
  text "2" at 5522.3,3069.2 h25
  text "33.47mil (0.850mm)" at 5660.65,3069.2 h25
  text "PTH" at 5925.8,3069.2 h25
  text "Round" at 6033.75,3069.2 h25
  text "Top Layer - Bottom Layer" at 6190.05,3069.2 h25
  text "D" at 5382.53,3059.21 h23.02
  text "6" at 5522.3,3017.41 h25
  text "35.43mil (0.900mm)" at 5660.65,3017.41 h25
  text "PTH" at 5925.8,3017.41 h25
  text "Round" at 6033.75,3017.41 h25
  text "Top Layer - Bottom Layer" at 6190.05,3017.41 h25
  text "4" at 5522.3,2965.62 h25
  text "39.37mil (1.000mm)" at 5660.65,2965.62 h25
  text "PTH" at 5925.8,2965.62 h25
  text "Round" at 6033.75,2965.62 h25
  text "Top Layer - Bottom Layer" at 6190.05,2965.62 h25
  text "16" at 5522.3,2913.83 h25
  text "41.34mil (1.050mm)" at 5660.65,2913.83 h25
  text "PTH" at 5925.8,2913.83 h25
  text "Round" at 6033.75,2913.83 h25
  text "Top Layer - Bottom Layer" at 6190.05,2913.83 h25
  text "7" at 5522.3,2862.03 h25
  text "45.28mil (1.150mm)" at 5660.65,2862.03 h25
  text "PTH" at 5925.8,2862.03 h25
  text "Round" at 6033.75,2862.03 h25
  text "Top Layer - Bottom Layer" at 6190.05,2862.03 h25
  text "4" at 5522.3,2810.24 h25
  text "47.24mil (1.200mm)" at 5660.65,2810.24 h25
  text "PTH" at 5925.8,2810.24 h25
  text "Round" at 6033.75,2810.24 h25
  text "Top Layer - Bottom Layer" at 6190.05,2810.24 h25
  text "2" at 5522.3,2758.45 h25
  text "49.21mil (1.250mm)" at 5660.65,2758.45 h25
  text "PTH" at 5925.8,2758.45 h25
  text "Round" at 6033.75,2758.45 h25
  text "Top Layer - Bottom Layer" at 6190.05,2758.45 h25
  text "4" at 5522.3,2706.66 h25
  text "51.18mil (1.300mm)" at 5660.65,2706.66 h25
  text "PTH" at 5925.8,2706.66 h25
  text "Round" at 6033.75,2706.66 h25
  text "Top Layer - Bottom Layer" at 6190.05,2706.66 h25
  text "1" at 5522.3,2654.87 h25
  text "60.00mil (1.524mm)" at 5660.65,2654.87 h25
  text "PTH" at 5925.8,2654.87 h25
  text "Round" at 6033.75,2654.87 h25
  text "Top Layer - Bottom Layer" at 6190.05,2654.87 h25
  text "2" at 5522.3,2603.07 h25
  text "94.49mil (2.400mm)" at 5660.65,2603.07 h25
  text "PTH" at 5925.8,2603.07 h25
  text "Round" at 6033.75,2603.07 h25
  text "Top Layer - Bottom Layer" at 6190.05,2603.07 h25
  text "A" at 5382.53,2593.08 h23.02
  text "3" at 5522.3,2551.28 h25
  text "118.11mil (3.000mm)" at 5660.65,2551.28 h25
  text "PTH" at 5925.8,2551.28 h25
  text "Round" at 6033.75,2551.28 h25
  text "Top Layer - Bottom Layer" at 6190.05,2551.28 h25
  text "B" at 5382.53,2541.29 h23.02
  text "235 Total" at 5522.3,2499.49 h25
  text ".Layer_Name" at 577,-858.49 h25
M17 Embedded Cavity:
  text ".Layer_Name" at 577,-858.49 h25
M18 Embedded Assembly:
  text ".Layer_Name" at 577,-858.49 h25
M19 Embedded Keepout:
  text ".Layer_Name" at 567,-858.49 h25

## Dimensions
0,0 to 3347.44,3347.44 on M2 Board Dimensions
0,0 to 3347.44,3347.44 on M2 Board Dimensions
0,-400 to 1000,-400 on M2 Board Dimensions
